// Mitsubishi GX Works2 project: 计时   PLC: FX1N/FX1NC

PROGRAM MAIN
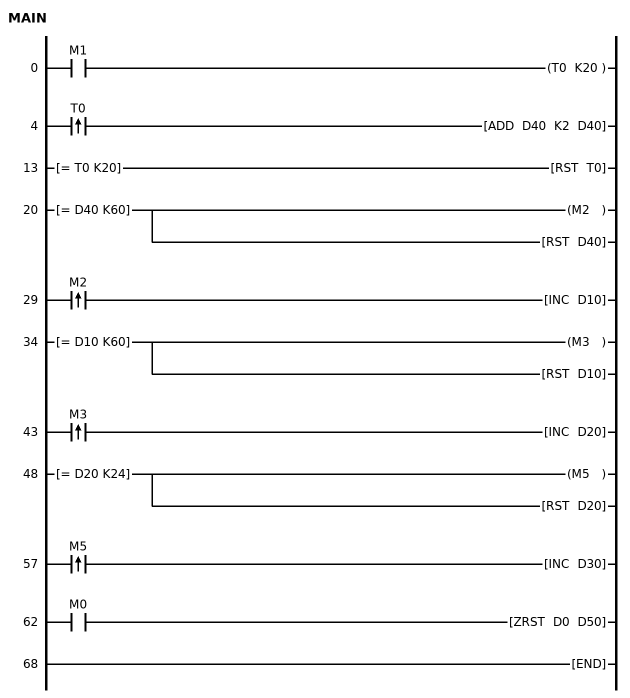
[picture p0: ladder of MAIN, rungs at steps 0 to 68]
0     LD      M1
      OUT     T0 K20
4     LDP     T0
      ADD     D40 K2 D40
        [note] 秒钟
13    LD=     T0 K20
      RST     T0
20    LD=     D40 K60
      OUT     M2
      RST     D40
29    LDP     M2
      INC     D10
34    LD=     D10 K60
      OUT     M3
      RST     D10
43    LDP     M3
      INC     D20
48    LD=     D20 K24
      OUT     M5
      RST     D20
57    LDP     M5
      INC     D30
62    LD      M0
      ZRST    D0 D50
68    END
END_PROGRAM
